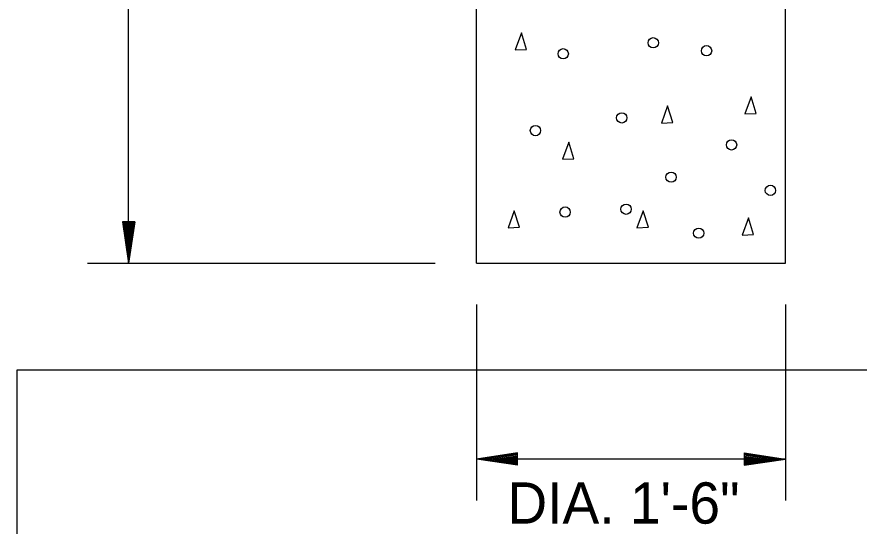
# Model space of a CAD drawing. Extents: x 418532 to 420296, y -565948 to -565286.
# Drawn here: x 418906.3 to 418998.3, y -565528 to -565472.5 of the extents above; entities that cross this region are included whole.
import ezdxf

# ---------------------------------------------------------------- set-up
doc = ezdxf.new("R2010")
doc.units = 0
doc.layers.add('R_Draft', color=7, linetype='Continuous')
doc.layers.add('Template', color=7, linetype='Continuous')

msp = doc.modelspace()

# ---------------------------------------------------------------- linework, layer by layer
at = {"layer": 'R_Draft'}
for p, q in [((418918.524, -565499.327), (418918.524, -565431.827)), ((418956.493, -565499.327), (418956.493, -565431.827)), ((418990.243, -565499.327), (418990.243, -565431.827)), ((418917.849, -565494.827), (418918.524, -565499.327)), ((418919.199, -565494.827), (418917.849, -565494.827)), ((418917.962, -565494.827), (418918.524, -565498.575)), ((418918.077, -565494.827), (418918.524, -565497.801)), ((418918.189, -565494.827), (418918.524, -565497.052)), ((418918.304, -565494.827), (418918.524, -565496.289)), ((418918.419, -565494.827), (418918.524, -565495.538)), ((418919.199, -565494.827), (418918.524, -565499.327)), ((418918.743, -565494.827), (418918.524, -565496.289)), ((418918.972, -565494.827), (418918.524, -565497.801)), ((418919.087, -565494.827), (418918.524, -565498.575)), ((418918.86, -565494.827), (418918.524, -565497.052)), ((418918.63, -565494.827), (418918.524, -565495.538)), ((418914.024, -565499.327), (418951.993, -565499.327)), ((418956.493, -565499.327), (418990.243, -565499.327)), ((418956.493, -565503.827), (418956.493, -565525.202)), ((418990.243, -565503.827), (418990.243, -565525.202)), ((418960.993, -565520.027), (418956.493, -565520.702)), ((418960.993, -565520.139), (418957.245, -565520.702)), ((418960.993, -565520.254), (418958.019, -565520.702)), ((418960.993, -565520.367), (418958.768, -565520.702)), ((418960.993, -565520.481), (418959.531, -565520.702)), ((418960.993, -565520.596), (418960.282, -565520.702)), ((418960.993, -565521.377), (418960.993, -565520.027)), ((418985.743, -565520.027), (418990.243, -565520.702)), ((418985.743, -565520.027), (418985.743, -565521.377)), ((418985.743, -565520.139), (418989.491, -565520.702)), ((418985.743, -565520.254), (418988.717, -565520.702)), ((418985.743, -565520.367), (418987.968, -565520.702)), ((418985.743, -565520.484), (418987.205, -565520.702)), ((418985.743, -565520.596), (418986.454, -565520.702)), ((418990.243, -565520.702), (418956.493, -565520.702)), ((418960.993, -565521.377), (418956.493, -565520.702)), ((418960.993, -565521.264), (418957.245, -565520.702)), ((418960.993, -565521.15), (418958.019, -565520.702)), ((418960.993, -565521.037), (418958.768, -565520.702)), ((418960.993, -565520.92), (418959.531, -565520.702)), ((418960.993, -565520.808), (418960.282, -565520.702)), ((418985.743, -565521.377), (418990.243, -565520.702)), ((418985.743, -565520.922), (418987.205, -565520.702)), ((418985.743, -565521.15), (418988.717, -565520.702)), ((418985.743, -565521.264), (418989.491, -565520.702)), ((418985.743, -565521.037), (418987.968, -565520.702)), ((418985.743, -565520.808), (418986.454, -565520.702))]:
    msp.add_line(p, q, dxfattribs=at)
for points in [[(418961.42, -565474.194), (418960.74, -565476.062), (418961.977, -565476.011), (418961.42, -565474.194)], [(418986.489, -565481.165), (418985.808, -565483.033), (418987.046, -565482.982), (418986.489, -565481.165)], [(418977.367, -565482.171), (418976.686, -565484.039), (418977.923, -565483.988), (418977.367, -565482.171)], [(418966.592, -565486.124), (418965.912, -565487.991), (418967.149, -565487.941), (418966.592, -565486.124)], [(418960.63, -565493.597), (418959.95, -565495.465), (418961.187, -565495.414), (418960.63, -565493.597)], [(418974.709, -565493.597), (418974.028, -565495.465), (418975.266, -565495.414), (418974.709, -565493.597)], [(418986.202, -565494.388), (418985.521, -565496.255), (418986.759, -565496.205), (418986.202, -565494.388)]]:
    msp.add_lwpolyline(points, dxfattribs=at)
for centre in [(418975.807, -565475.282), (418981.625, -565476.144), (418965.976, -565476.483), (418972.359, -565483.474), (418962.939, -565484.86), (418984.354, -565486.42), (418977.746, -565489.942), (418988.592, -565491.379), (418972.831, -565493.442), (418966.182, -565493.75), (418980.763, -565496.05)]:
    msp.add_circle(centre, 0.562, dxfattribs=at)
at = {"layer": 'Template'}
msp.add_lwpolyline([(419214.195, -565511.016), (418906.322, -565511.016), (418906.322, -565641.34), (419214.195, -565641.34)], close=True, dxfattribs=at)

# ---------------------------------------------------------------- texts
at = {"layer": 'R_Draft'}
msp.add_text('DIA. 1\'-6"', height=4.5, dxfattribs=at).set_placement((418959.875, -565527.742))

doc.saveas('drawing.dxf')
